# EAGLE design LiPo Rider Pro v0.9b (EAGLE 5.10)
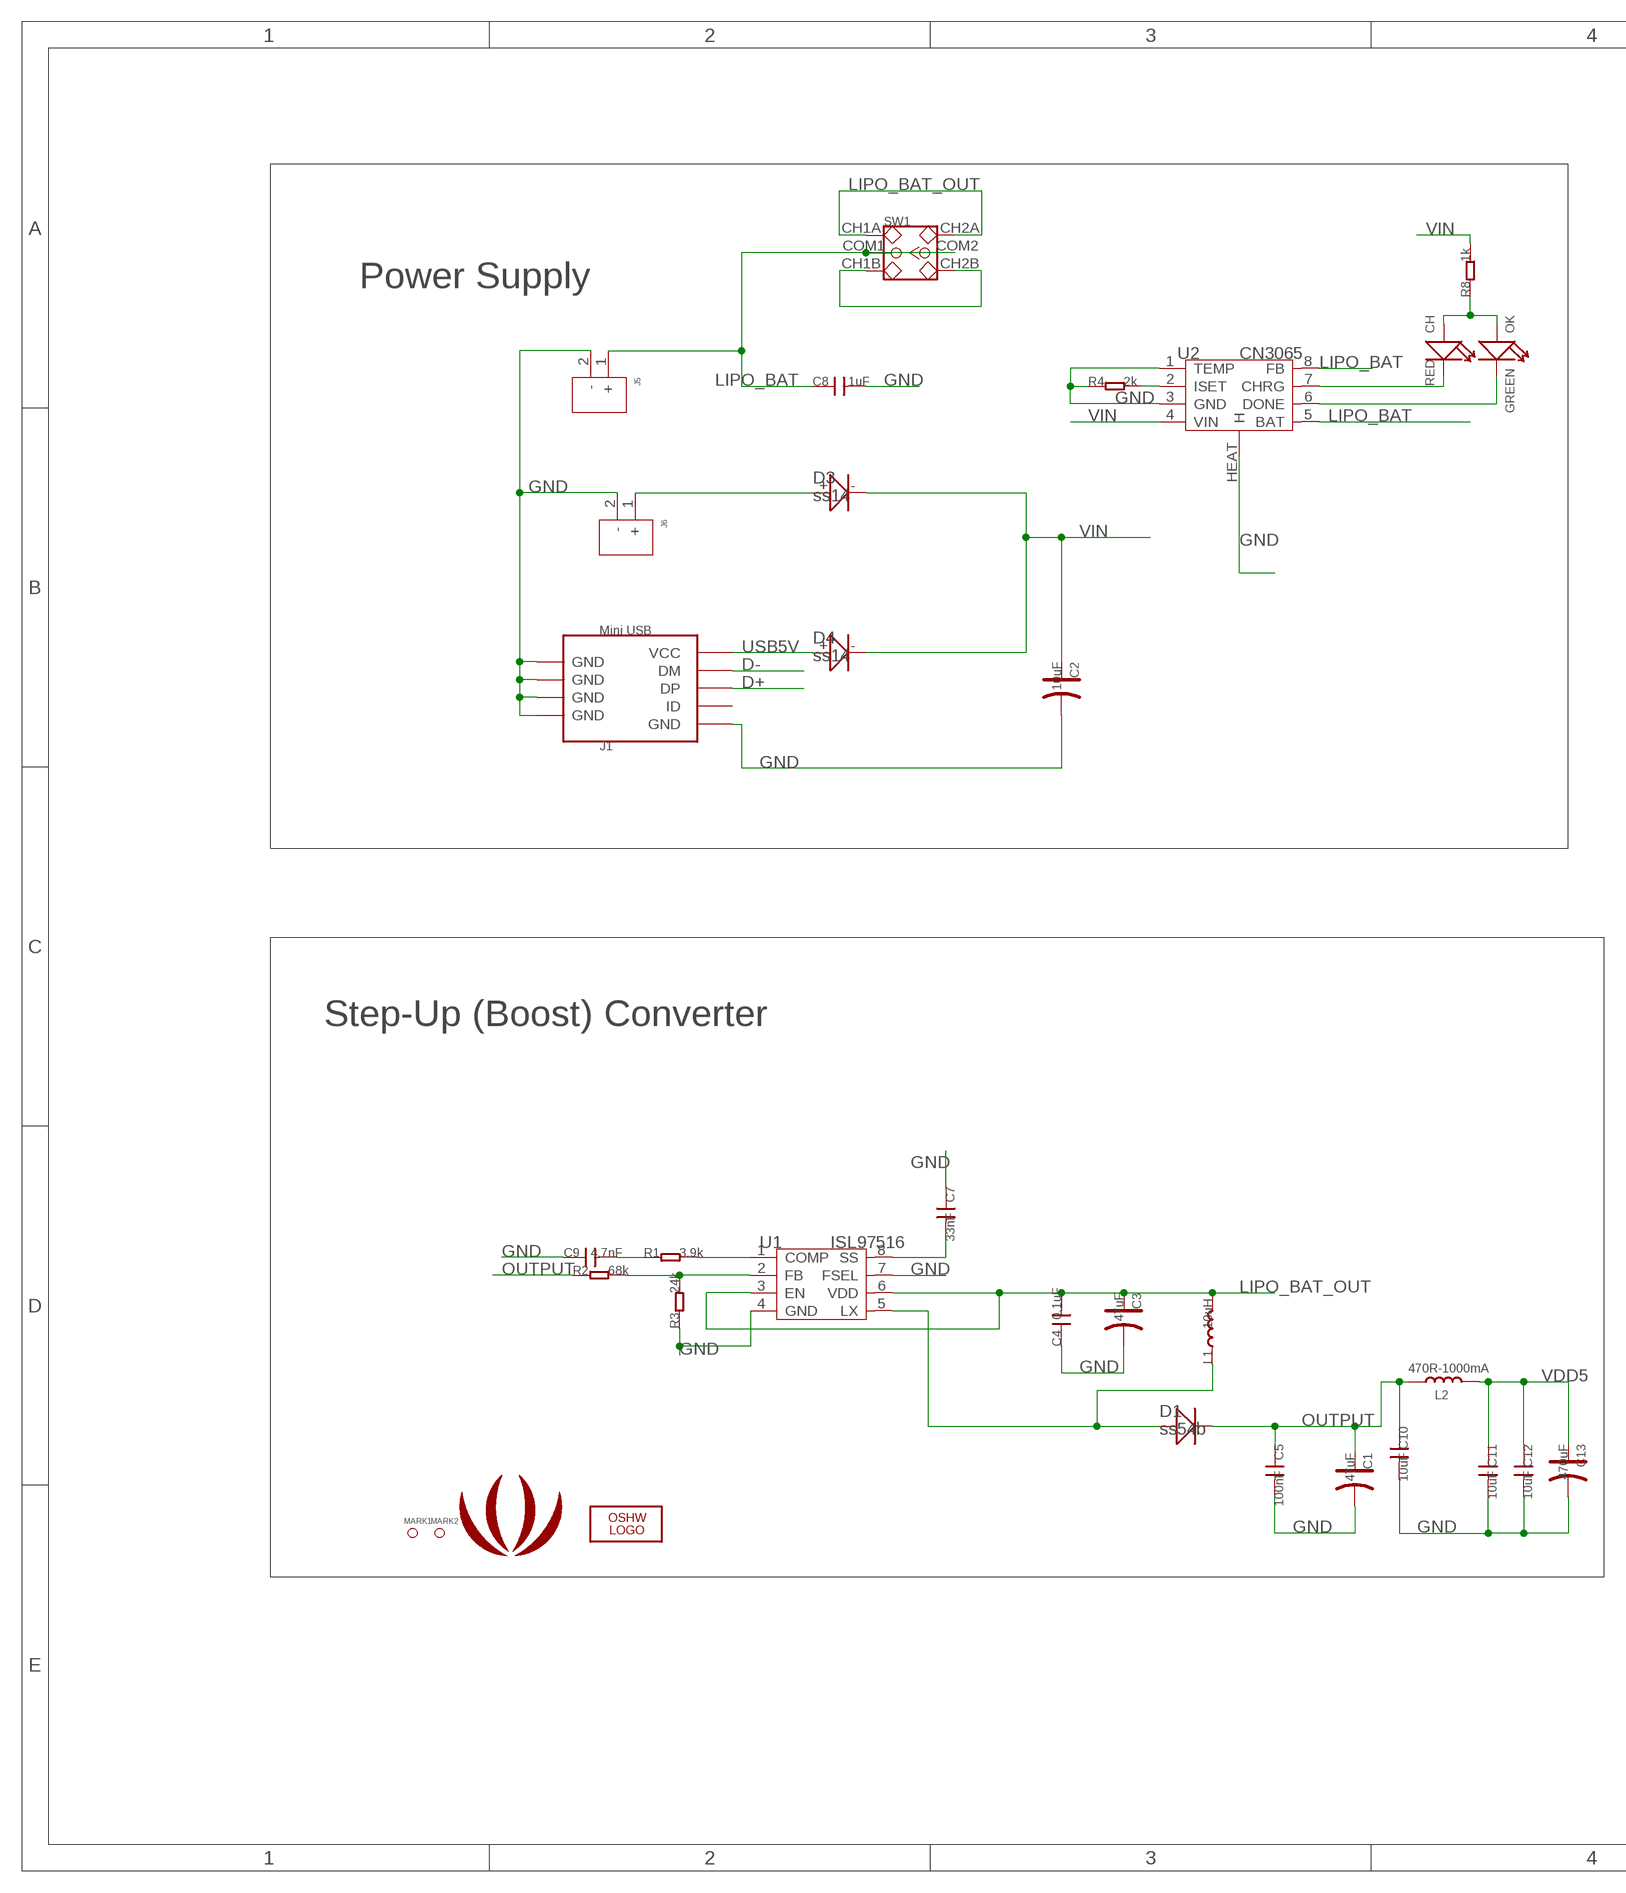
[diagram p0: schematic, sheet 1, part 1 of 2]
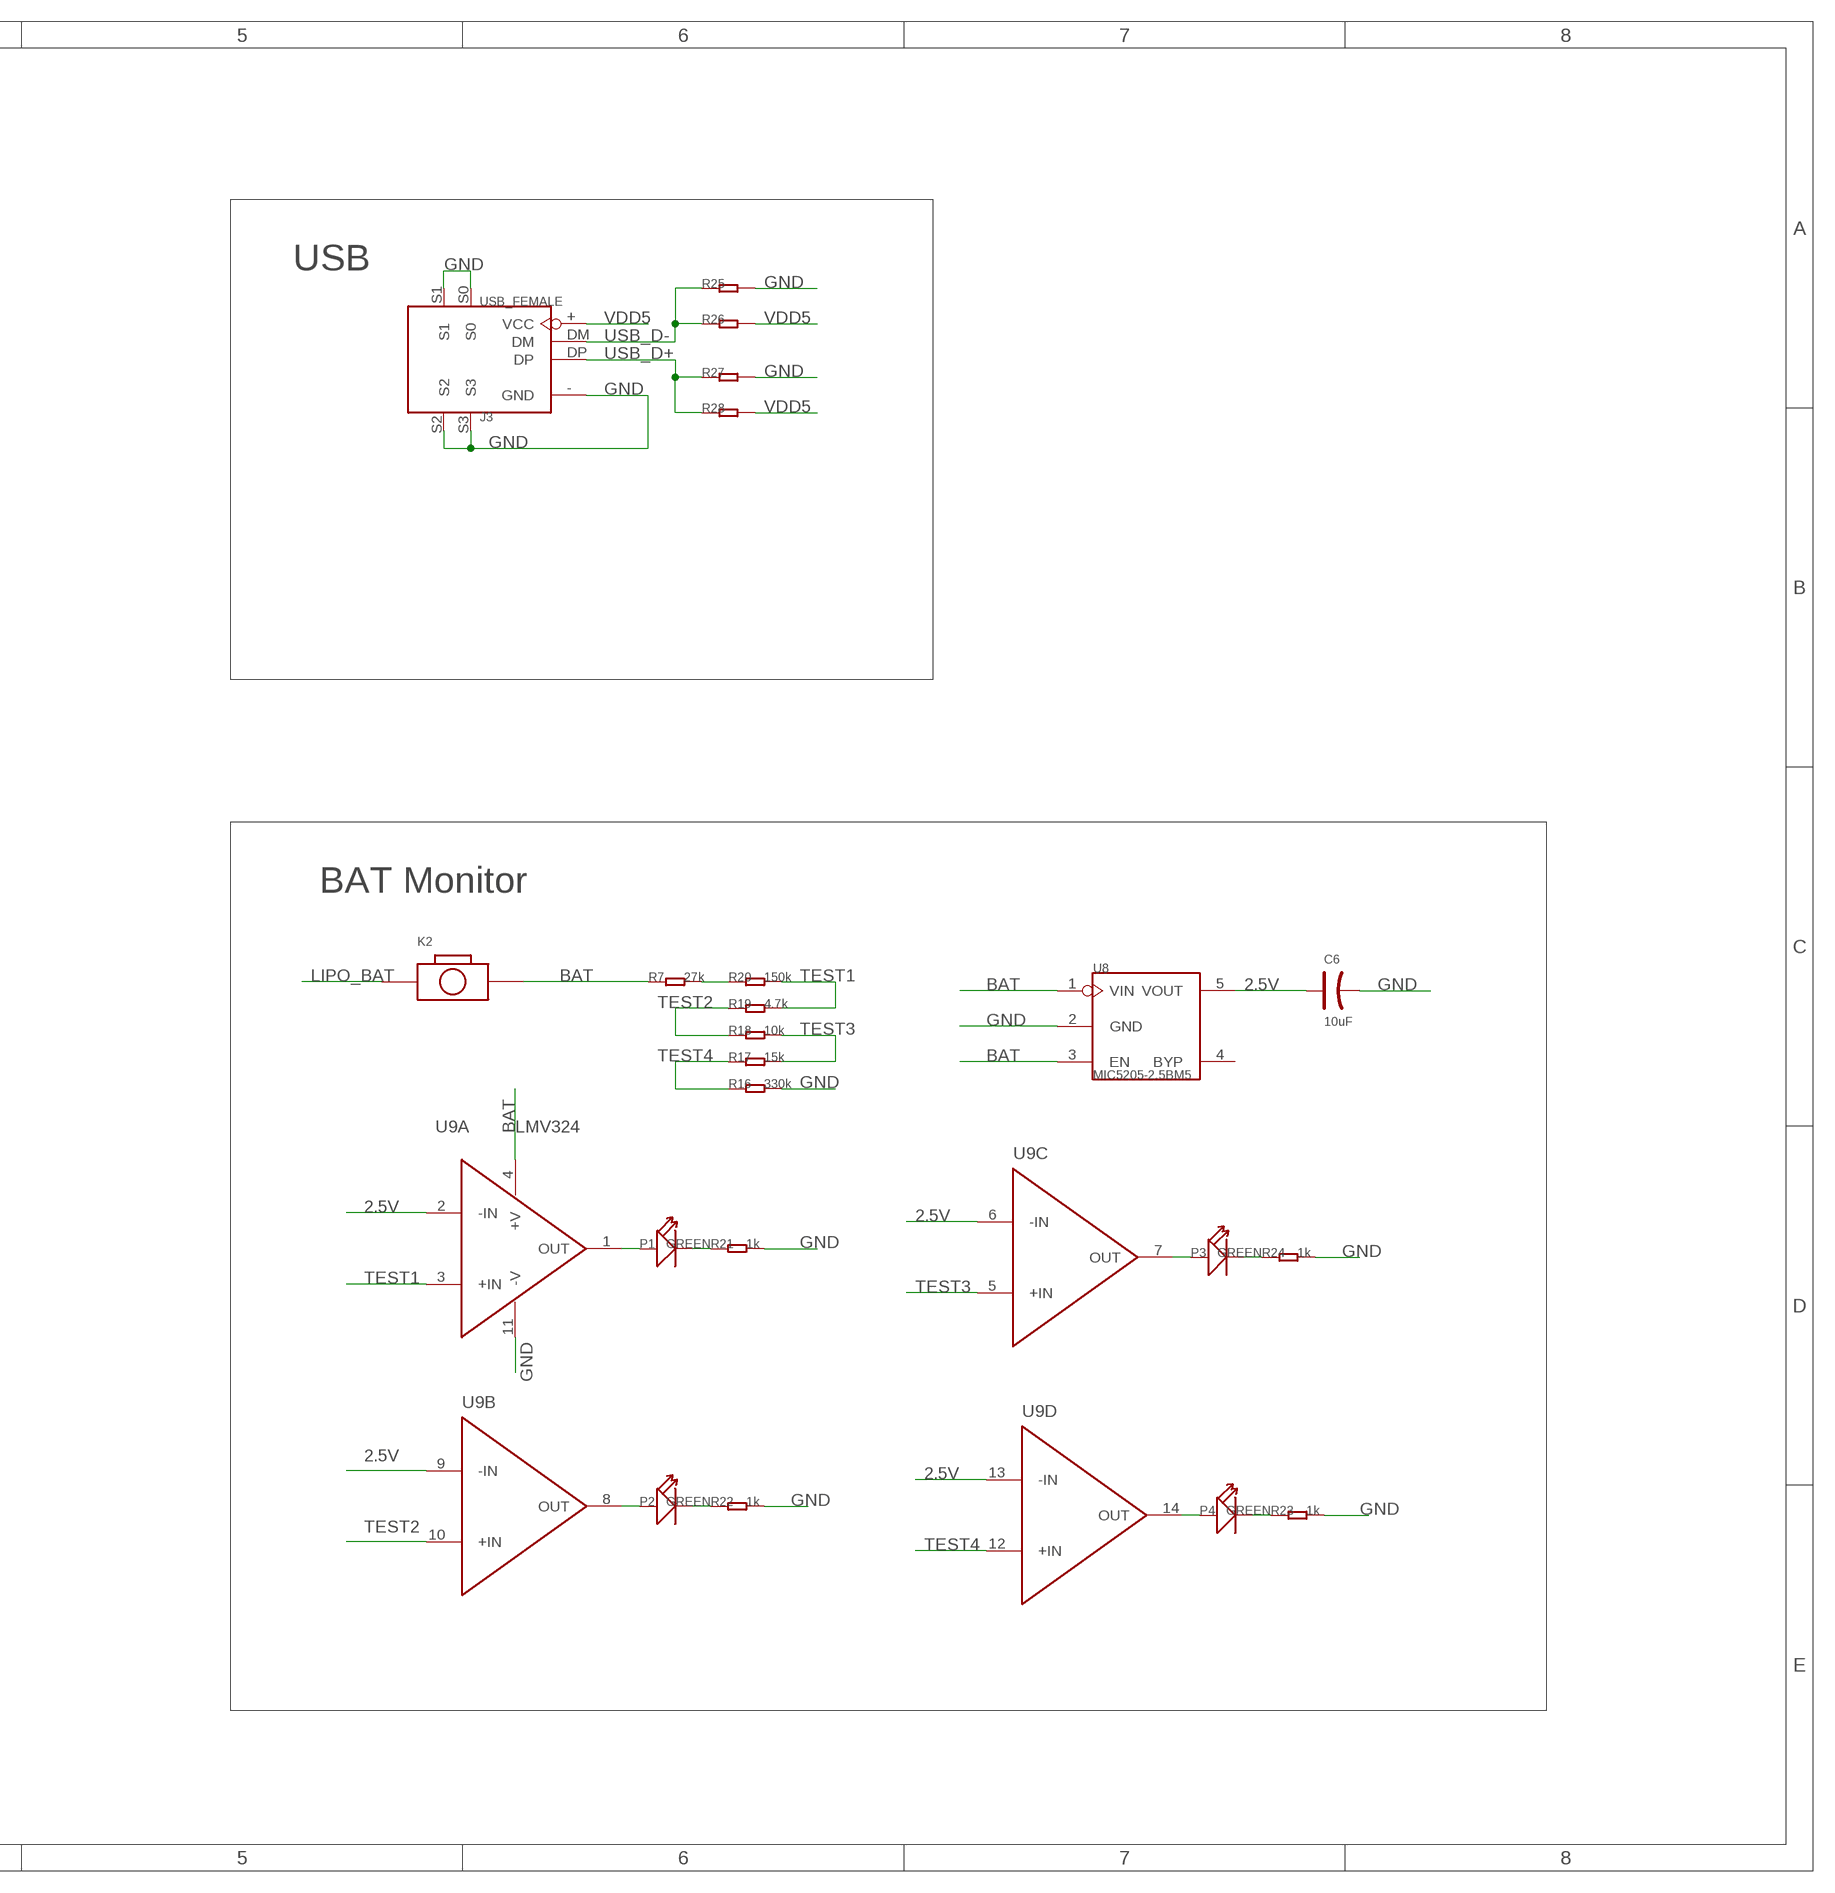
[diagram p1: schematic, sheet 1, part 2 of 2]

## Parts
C1  47uF  CAP_AVX_C  [AVX-C]
C2  10uF  CAP_AVX_B  [AVX-B]
C3  47uF  CAP_AVX_C  [AVX-C]
C4  0.1uF  C-0603  [0603]
C5  100nF  C-0603  [0603]
C6  10uF  CAP_AVX_B  [AVX-B]
C7  33nF  C-0603  [0603]
C8  1uF  C-0805  [0805]
C9  4.7nF  C-0603  [0603]
C10  10uF  C-0805  [0805]
C11  10uF  C-0805  [0805]
C12  10uF  C-0805  [0805]
C13  470uF  CAP_AVX_D  [AVX-D]
CH  RED  LED-0603  [D0603]
D1  ss54b  D-MBRS240LT3  [SMB]
D3  ss14  010-D2010  [D2010]
D4  ss14  010-D2010  [D2010]
J1  Mini USB  USB-MINIUSB-5P-STRONG  [MINI-5P]
J3  USB_FEMALE  USB-FEMALE-13.2X14.5  [FEMALE-13.2X14.5]
J5  JST-2P-POWER-SMD'2.0'  [2P-SMD-2.0-8X7.8]
J6  JST-2P-POWER-SMD'2.0'  [2P-SMD-2.0-8X7.8]
K2  BOTTON-2P-DIP  [2P-LEADED-90-3.56X7.62]
L1  10uH  L-PIO73  [PIO73]
L2  470R-1000mA  L0805  [0805]
LOGO1  LOGO-OSHW-FILLX0200-NT  [OSHW_FILLX200_NOTEXT]
MARK1  PAD-MARK  [ROUND-MARK-0.635]
MARK2  PAD-MARK  [ROUND-MARK-0.635]
OK  GREEN  LED-0603  [D0603]
P1  GREEN  LED-0603  [D0603]
P2  GREEN  LED-0603  [D0603]
P3  GREEN  LED-0603  [D0603]
P4  GREEN  LED-0603  [D0603]
R1  3.9k  R-0603  [0603]
R2  68k  R-0603  [0603]
R3  24k  R-0603  [0603]
R4  2k  R-0603  [0603]
R7  27k  R-0603  [0603]
R8  1k  R-0603  [0603]
R16  330k  R-0603  [0603]
R17  15k  R-0603  [0603]
R18  10k  R-0603  [0603]
R19  4.7k  R-0603  [0603]
R20  150k  R-0603  [0603]
R21  1k  R-0603  [0603]
R22  1k  R-0603  [0603]
R23  1k  R-0603  [0603]
R24  1k  R-0603  [0603]
R25  R-0204/5  [0204/5]
R26  R-0204/5  [0204/5]
R27  R-0204/5  [0204/5]
R28  R-0204/5  [0204/5]
SW1  SWITCH-2CH-6P'90'  [6P-LEADED-2CH-2.54-90-3.6X9.0]
U1  ISL97516  [MSOP8]
U2  CN3065  [DFN8]
U8  MIC5205-2.5BM5  MIC5025-SOT23-5  [SOT23-5]
U9  LMV324  [SO014]
U$1  LOGO-SEEEDSTUDIO-SILK  [LOGO_SILK]

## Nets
2.5V: C6.+ U8.5(VOUT) U9.2(A:-IN) U9.6(C:-IN) U9.9(B:-IN) U9.13(D:-IN)
BAT: K2.P$2 R7.1 U8.1(VIN) U8.3(EN) U9.4(A:+V)
CH: SW1.CH1B SW1.CH2B
D+: J1.3(DP)
D-: J1.2(DM)
GND: C1.- C2.- C3.- C4.1 C5.2 C6.- C7.1 C8.2 C9.1 C10.2 C11.2 C12.2 C13.- J1.5(GND) J1.GND@1(GND) J1.GND@2(GND) J1.GND@3(GND) J1.GND@4(GND) J3.-(GND) J3.S0 J3.S1 J3.S2 J3.S3 J5.2(-) J6.2(-) R3.1 R4.1 R16.2 R21.2 R22.2 R23.2 R24.2 R25.2 R27.2 U1.4(GND) U1.7(FSEL) U2.1(TEMP) U2.3(GND) U2.HEAT(H) U8.2(GND) U9.11(A:-V)
LIPO_BAT: C8.1 J5.1(+) K2.P$1 SW1.COM1 SW1.COM2 U2.5(BAT) U2.8(FB)
LIPO_BAT_OUT: C3.+ C4.2 L1.2 SW1.CH1A SW1.CH2A U1.3(EN) U1.6(VDD)
N$1: C7.2 U1.8(SS)
N$2: D1.+ L1.1 U1.5(LX)
N$3: D3.+ J6.1(+)
N$4: R1.2 U1.1(COMP)
N$5: C9.2 R1.1
N$6: R2.2 R3.2 U1.2(FB)
N$7: R4.2 U2.2(ISET)
N$8: CH.- U2.7(CHRG)
N$9: OK.- U2.6(DONE)
N$10: CH.+ OK.+ R8.1
N$20: R7.2 R20.1
N$25: P3.+ U9.7(C:OUT)
N$26: P4.+ U9.14(D:OUT)
N$28: P1.+ U9.1(A:OUT)
N$31: P2.+ U9.8(B:OUT)
N$33: P1.- R21.1
N$35: P2.- R22.1
N$36: P4.- R23.1
N$37: P3.- R24.1
OUTPUT: C1.+ C5.1 C10.1 D1.- L2.1 R2.1
TEST1: R19.2 R20.2 U9.3(A:+IN)
TEST2: R18.1 R19.1 U9.10(B:+IN)
TEST3: R17.2 R18.2 U9.5(C:+IN)
TEST4: R16.1 R17.1 U9.12(D:+IN)
USB5V: D4.+ J1.1(VCC)
USB_D+: J3.DP R27.1 R28.1
USB_D-: J3.DM R25.1 R26.1
VDD5: C11.1 C12.1 C13.+ J3.+(VCC) L2.2 R26.2 R28.2
VIN: C2.+ D3.- D4.- R8.2 U2.4(VIN)
Unconnected: J1.4(ID) U8.4(BYP)

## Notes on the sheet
- USB
- Power Supply
- BAT Monitor
- Step-Up (Boost) Converter

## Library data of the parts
C1 C3 C13 = Discrete:CAP*: Electrolytic Capacitors,Tantalum Capacitors and Super Capacitors
C2 C6 = Discreter:CAP*: Electrolytic Capacitors,Tantalum Capacitors and Super Capacitors
C4 C5 C7 C9-C12 = Discrete:C*: Ceramic Capacitors
C8 = Discreter:C*: Ceramic Capacitors
CH OK = Discrete:LED*
D1 = Discrete:D*
D3 D4 = Discrete:010-D*
J1 = Connector:USB-MINIUSB-5P
J3 = Connector:USB-FEMALE
J5 J6 = Connector:JST-2P-POWER-SMD
K2 = Discreter:BOTTON-2P
L1 L2 = Discrete:L*
LOGO1 = Logo:LOGO-OSHW-FILL
MARK1 MARK2 = Discreter:PAD-MARK
P1-P4 = Discreter:LED*
R1-R4 R8 R25-R28 = Discrete:R*
R7 R16-R24 = Discreter:R*
SW1 = Discrete:SWITCH-2CH-6P
U1 = IC:ISL97516
U2 = IC:CN3065
U8 = IC:MIC5025
U9 = IC (Miao Albert's conflicted copy 2011-05-27):LMV324
U$1 = Logo:LOGO-SEEEDSTUDIO

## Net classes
0 default: width 0.203 mm, drill 0.305 mm, clearance 0.127 mm

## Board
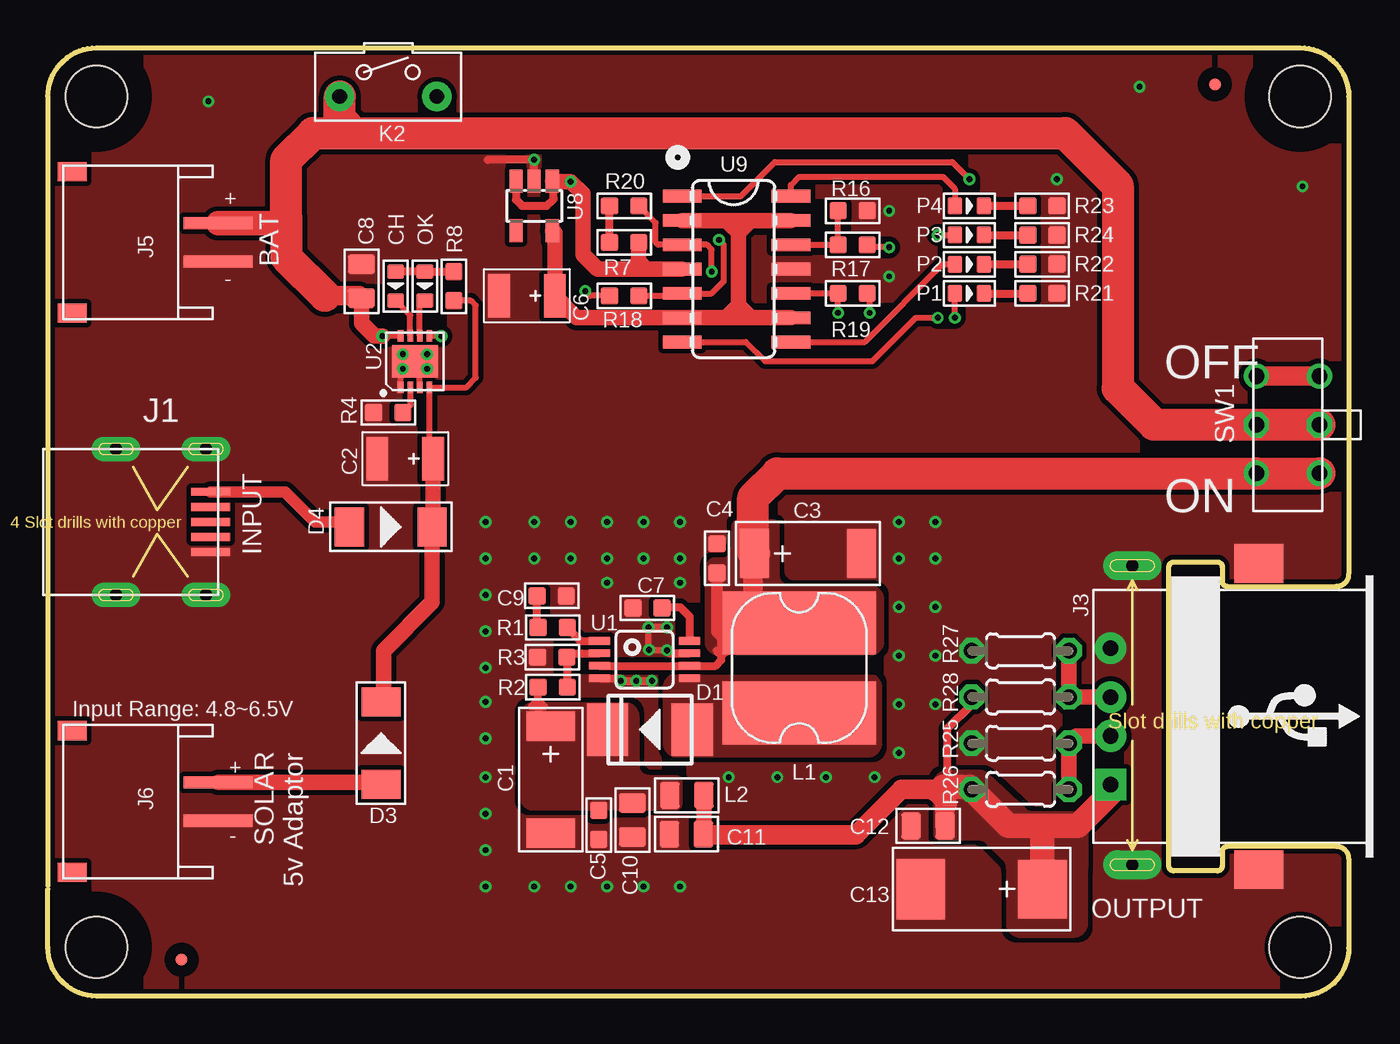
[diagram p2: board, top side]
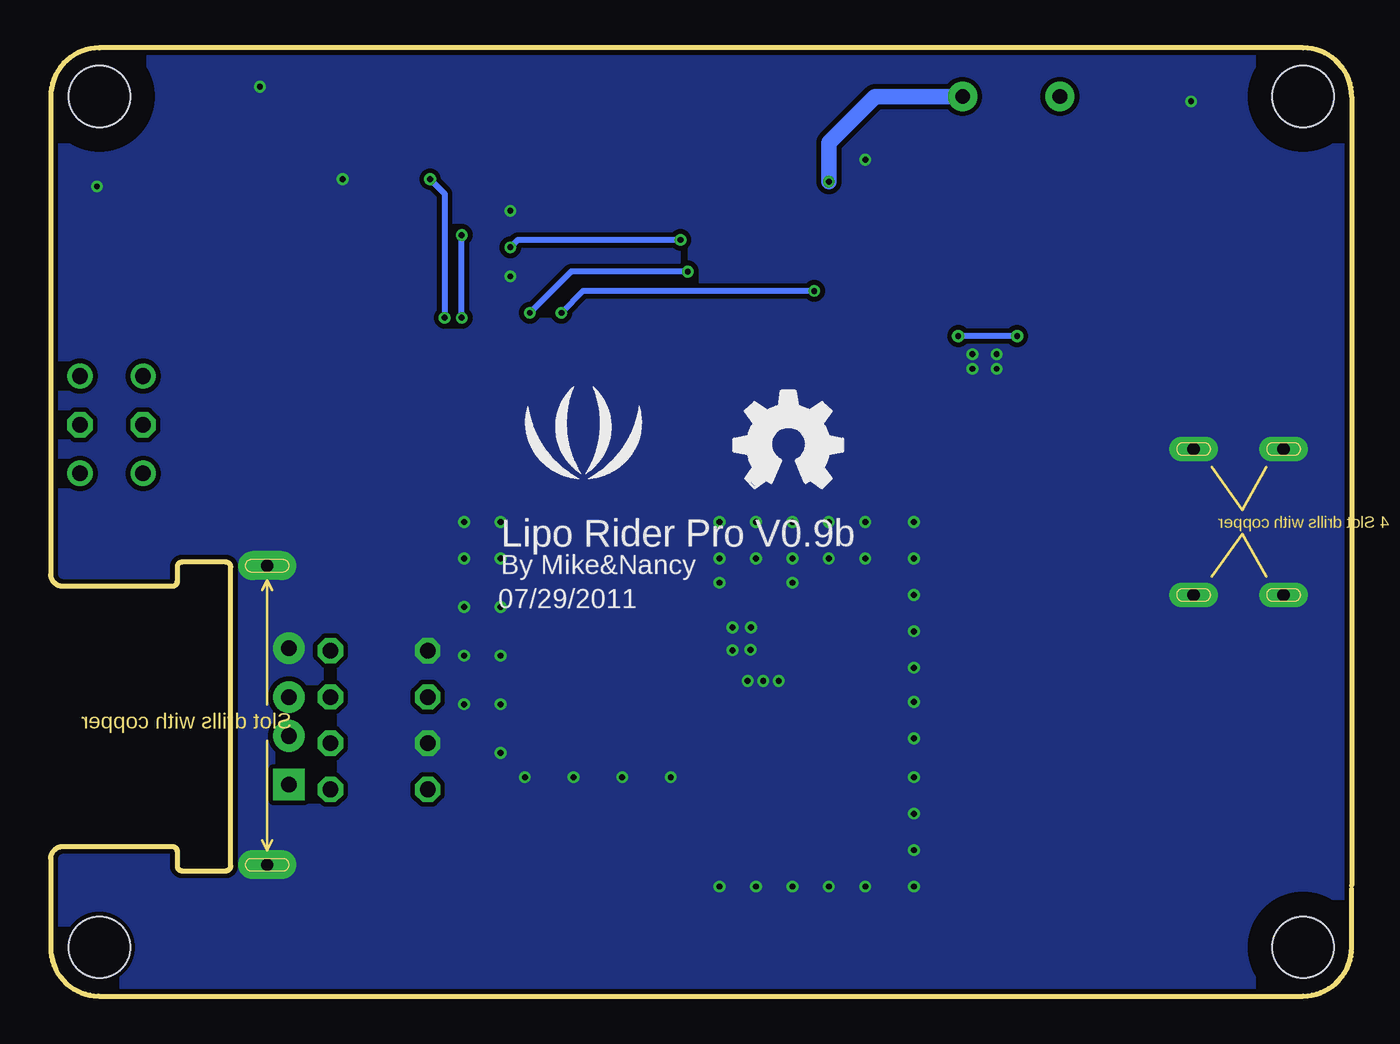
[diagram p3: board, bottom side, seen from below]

Size 67.94 x 49.53 mm. Coordinates in mm from the lower left corner, seen from the top.
Outline: 0,5.78 0,46.99 arc-90 2.54,49.53 65.41,49.53 arc-90 67.94,46.99 67.94,22.04 arc-90 67.31,21.4 61.59,21.4 arc-90 61.34,21.65 61.34,22.42 arc90 61.09,22.67 58.8,22.67 arc90 58.55,22.42 58.55,6.79 arc90 58.8,6.54 61.09,6.54 arc90 61.34,6.79 61.34,7.56 arc-90 61.59,7.81 67.31,7.81 arc-90 67.94,7.18 67.94,2.5 arc-90 65.44,0 2.54,0 arc-90 0,2.54 0,5.59
Copper layers (1*16): Top 0.035mm / dielectric 1.5mm / Bottom 0.035mm
Design rules "SeeedStudio_rule_no_angle_090911 *": minimum track width 6mil, minimum drill 12mil, track to track 6mil, track to pad 6mil, pad to pad 6mil, via to via 6mil, smd to smd 0mil, copper to edge 10mil, drill to drill 10mil, minimum pad ring 10mil, minimum via ring 6mil, stop-mask expansion 2mil, vias tented up to drill 25mil, thermal gap 10mil
Holes 3.2 mm at 2.54,46.99 2.54,2.54 65.41,46.99 65.41,2.54
tRestrict: area 0,44.5 to 5.1,49.5; area 62.9,44.5 to 67.9,49.5; area 0,0 to 5.1,5.1; area 35.6,17 to 43.4,17.6; area 35.2,17 to 35.8,17.2
bRestrict: area 62.9,44.5 to 67.9,49.5; area 0,0 to 5.1,5.1; area 0,44.5 to 5.1,49.5

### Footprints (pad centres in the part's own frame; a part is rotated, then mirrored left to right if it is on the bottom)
AVX-C = smd 1.524 x 2.54: + -2.794,0; - 2.794,0
AVX-B = smd 1.143 x 2.286: + -1.46,0; - 1.46,0
0603 = smd 0.889 x 0.889: 1 -0.762,0; 2 0.762,0
0805 = smd 1.016 x 1.397: 1 -0.889,0; 2 0.889,0
AVX-D = smd 2.54 x 3.048: + -3.175,0 | smd 2.54 x 3.175: - 3.175,0
D0603 = smd 0.762 x 0.889: + -0.762,0; - 0.762,0
SMB = smd 2.159 x 2.743: + 2.21,0; - -2.21,0
D2010 = smd 1.524 x 2.032: + -2.159,0; - 2.159,0
MINI-5P = smd 2.032 x 0.406: 1 0.381,-1.575; 2 0.381,-0.787; 3 0.381,0; 4 0.381,0.787; 5 0.381,1.575 | drill 0.635 pad 1.27 long: GND@1 0.635,3.81; GND@2 5.334,3.81; GND@3 5.334,-3.81; GND@4 0.635,-3.81
FEMALE-13.2X14.5 = drill 0.813 pad 1.651 square: + 0.889,-3.556 | drill 0.813 pad 1.651 round: - 0.889,3.556; DM 0.889,-1.016; DP 0.889,1.016 | smd 2.54 x 2.032: S0 8.636,8.001; S3 8.636,-8.001 | drill 0.635 pad 1.524 long: S1 2.032,7.874; S2 2.032,-7.747
2P-SMD-2.0-8X7.8 = smd 0.635 x 3.6: 1 -1,5.08; 2 1,5.08 | smd 1 x 1.5: P$1 -3.7,-2.54; P$2 3.7,-2.54
2P-LEADED-90-3.56X7.62 = drill 0.762 pad 1.524 round: P$1 0,2.54; P$2 0,-2.54
PIO73 = smd 8 x 3.3: 1 0,2.35; 2 0,-2.35
ROUND-MARK-0.635 = smd 0.635 x 0.635: P$1 0,0
0204/5 = drill 0.813 octagon: 1 -2.54,0; 2 2.54,0
6P-LEADED-2CH-2.54-90-3.6X9.0 = drill 0.813 pad 1.27 round: CH1A -2.54,-1.65; CH1B 2.54,-1.65; CH2A -2.54,1.65; CH2B 2.54,1.65 | drill 0.813 pad 1.27 octagon: COM1 0,-1.65; COM2 0,1.65
MSOP8 = smd 0.4 x 1.1: 1 -0.975,-2.35; 2 -0.325,-2.35; 3 0.325,-2.35; 4 0.975,-2.35; 5 0.975,2.35; 6 0.325,2.35; 7 -0.325,2.35; 8 -0.975,2.35
DFN8 = smd 0.3 x 0.6: 1 -0.75,-1.35; 2 -0.25,-1.35; 3 0.25,-1.35; 4 0.75,-1.35; 5 0.75,1.35; 6 0.25,1.35; 7 -0.25,1.35; 8 -0.75,1.35 | smd 2.4 x 1.7: HEAT 0,0
SOT23-5 = smd 0.69 x 1.2: 1 -0.95,-1.3; 2 0,-1.3; 3 0.95,-1.3; 4 0.95,1.3; 5 -0.95,1.3
SO014 = smd 0.66 x 2.032: 1 -3.175,-2.68; 2 -1.905,-2.68; 3 -0.635,-2.68; 4 0.635,-2.68; 5 1.905,-2.68; 6 3.175,-2.68; 7 4.445,-2.68; 8 4.445,2.997; 9 3.175,2.997; 10 1.905,2.997; 11 0.635,2.997; 12 -0.635,2.997; 13 -1.905,2.997; 14 -3.175,2.997

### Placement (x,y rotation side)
C1  26.26,11.3 270 top
C2  18.67,28.07 180 top
C3  39.7,23.11 0 top
C4  34.95,22.86 270 top
C5  28.78,8.94 270 top
C6  25.02,36.58 180 top
C7  31.32,20.27 0 top
C8  16.38,37.34 90 top
C9  26.31,20.9 180 top
C10  30.53,9.19 270 top
C11  33.35,8.46 180 top
C12  45.97,8.89 180 top
C13  48.77,5.59 180 top
CH  18.16,37.08 270 top
D1  31.45,13.92 0 top
D3  17.4,13.21 90 top
D4  17.91,24.51 0 top
J1  8.89,24.77 180 top
J3  54.61,14.61 0 top
J5  3.81,39.37 270 top
J6  3.81,10.16 270 top
K2  17.78,46.99 90 top
L1  39.24,17.14 180 top
L2  33.38,10.49 0 top
LOGO1  32.26,26.54 0 bottom
MARK1  6.99,1.91 0 top
MARK2  60.96,47.62 0 top
OK  19.68,37.08 270 top
P1  48.13,36.7 0 top
P2  48.13,38.23 0 top
P3  48.13,39.75 0 top
P4  48.13,41.27 0 top
R1  26.37,19.25 0 top
R2  26.37,16.13 0 top
R3  26.34,17.7 0 top
R4  17.78,30.48 0 top
R7  30.1,39.37 180 top
R8  21.21,37.08 270 top
R16  42.04,41.02 0 top
R17  42.04,39.24 0 top
R18  30.1,36.58 0 top
R19  42.04,36.7 0 top
R20  30.1,41.27 0 top
R21  51.94,36.7 0 top
R22  51.94,38.23 0 top
R23  51.94,41.27 0 top
R24  51.94,39.75 0 top
R25  50.8,13.21 180 top
R26  50.8,10.79 180 top
R27  50.8,18.03 180 top
R28  50.8,15.62 180 top
SW1  64.77,29.84 90 top
U1  31.17,17.58 270 top
U2  19.18,33.15 0 top
U8  25.4,41.27 180 top
U9  35.81,38.61 270 top
U$1  40.13,28.7 0 bottom

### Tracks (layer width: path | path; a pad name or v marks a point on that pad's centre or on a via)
2.5V
  Top 0.813: U8.5 26.48,39.84 C6.+ 27.62,35.43 U9.6 35.43,35.43 | 36.07,35.43 36.7,35.43 | 36.7,35.43 U9.9 | 36.07,40.51 U9.2 | 36.07,40.51 U9.13 | 35.43,35.43 36.07,35.43 | 36.07,35.43 36.07,36.07 | 36.07,39.88 36.07,40.51 | 36.07,39.88 35.56,40.39 | 36.07,39.88 36.58,40.39 | 36.07,36.07 36.7,35.43 | 36.07,36.07 36.07,39.88 | 35.43,35.43 36.07,36.07
BAT  (via drill 0.3 pad 0.61)
  Top 0.406: U8.3 24.45,41.59 24.77,41.27 26.06,41.27 26.42,41.63 26.42,42.51 U8.1
  Top 0.813: 30.48,37.97 28.7,37.97 27.94,38.73 27.94,41.91 v27.3,42.55 26.38,42.55 U8.1 | 30.48,37.97 U9.4 | 30.86,38.35 R7.1 | 30.86,38.35 31.11,38.1 | 30.48,37.97 30.86,38.35
  Bottom 0.813: K2.P$2 24.89,46.99 27.3,44.58 v27.3,42.55
CH
  Top 1.016: SW1.CH2B SW1.CH1B
GND  (via drill 0.3)
  Top 0.305: U2.3 19.43,32.38 v19.81,32.77 | U2.1 18.43,32.65 v18.54,32.77 | v32.33,18.06 31.39,18.06 31.37,18.03 31.37,19.3 32.26,19.3 32.38,19.18
  Top 0.406: U8.2 v25.4,43.69 22.99,43.69 | 32.99,17.9 U1.7 | v32.33,18.06 32.49,17.9 32.99,17.9 | 32.99,17.9 32.99,17.91 32.77,17.91 | U1.4 29.78,16.6 v29.92,16.46 30.68,16.46 30.73,16.51 | v30.73,16.46 31.45,16.46 31.5,16.51
  other vias: 52.7,42.67 43.94,41.02 43.94,37.59 65.53,42.29 8.38,46.74 57.02,47.5 22.86,11.43 22.86,13.46 22.86,15.37 22.86,19.05 22.86,9.53 22.86,7.62 22.86,20.95 31.39,18.08 22.86,17.14 22.86,5.71 25.4,5.71 27.3,5.71 29.21,5.71 33.02,5.71 31.11,5.71 22.86,22.86 25.4,22.86 27.3,22.86 29.21,22.86 31.11,22.86 33.02,22.86 33.02,21.59 29.21,21.59 33.02,24.77 31.11,24.77 29.21,24.77 27.3,24.77 25.4,24.77 22.86,24.77 44.45,24.77 44.45,22.86 44.45,20.32 44.45,17.78 44.45,15.24 44.45,12.7 46.35,24.77 46.35,15.24 46.35,17.78 46.35,20.32 46.35,22.86 32.33,19.25 31.37,19.25 31.55,16.46 18.54,33.53 19.81,33.53 35.56,11.43 38.1,11.43 40.64,11.43 43.18,11.43
  pour Bottom: -6.99,48.26 -5.71,48.26 -5.71,46.99 -6.99,46.99
  pour Top (isolate 0.254, rank 5, no thermals): -1.27,50.16 70.48,50.16 70.48,-1.27 -1.27,-1.27
  pour Bottom (isolate 0.254, rank 5, no thermals): -1.27,50.16 70.48,50.16 70.48,-1.27 -1.27,-1.27
LIPO_BAT  (via drill 0.3 pad 0.64)
  Top 0.305: v20.55,34.47 20,34.47 arc-45 U2.5 | U2.8 17.8,34.5 arc45 v17.48,34.47
  Top 0.406: SW1.COM1
  Top 0.813: v17.48,34.47 17.07,34.47 16.38,35.15 C8.1
  Top 1.016: 14.48,36.58 16.26,36.58 C8.1
  Top 1.27: J5.1 12.18,40.37 12.45,40.64
  Top 1.676: 15.24,45.72 K2.P$1 | 15.24,45.72 15.24,45.62 14.71,45.09 | 15.24,45.72 15.37,45.72 16,45.09 | 14.71,45.09 16,45.09 | 16,45.09 53.13,45.09 55.88,42.34 55.88,31.75 57.78,29.84 SW1.COM2 SW1.COM1 | 14.71,45.09 13.84,45.09 12.45,43.69 12.45,40.64 12.45,38.61 14.48,36.58
  Bottom 0.305: v17.48,34.47 v20.55,34.47
LIPO_BAT_OUT
  Top 0.406: U1.3 U1.6 34.89,17.25 35.18,17.55 35.18,17.78 | L1.2 38.92,19.18 36.58,19.18 | 35.18,17.78 35.18,18.8 | 36.58,19.18 35.43,19.18 35.12,18.86 35.05,18.8 36.2,18.8 36.58,19.18 | 35.18,17.78 35.05,17.91 | 35.05,17.91 34.92,18.03 | 35.18,17.78 35.43,18.03 | 38.73,19.05 36.2,19.05 35.05,17.91
  Top 0.61: C4.2 34.95,19.02 35.12,18.86 38.54,18.86 38.73,19.05 | 36.58,19.18 36.58,19.43 36.83,19.68
  Top 1.016: 36.83,19.68 36.83,23.19
  Top 1.676: C3.+ 36.83,23.19 36.83,26.04 38.1,27.3 SW1.CH2A SW1.CH1A
  pour Top (isolate 0.254, no thermals): 43.56,20.7 arc90 42.93,21.34 38.73,21.34 arc-90 38.1,21.97 38.1,24.51 arc90 37.85,24.77 36.07,24.77 arc90 35.81,24.51 35.81,23.5 arc-90 35.18,22.86 35.05,22.86 arc90 34.42,22.23 34.42,18.54 arc90 35.05,17.91 42.93,17.91 arc90 43.56,18.54
  pour Top (isolate 0.254, no thermals): 43.56,20.7 arc90 42.93,21.34 38.73,21.34 arc-90 38.1,21.97 38.1,24.51 arc90 37.85,24.77 36.07,24.77 arc90 35.81,24.51 35.81,23.5 arc-90 35.18,22.86 35.05,22.86 arc90 34.42,22.23 34.42,18.54 arc90 35.05,17.91 42.93,17.91 arc90 43.56,18.54
N$1
  Top 0.406: U1.8 33.52,19.82 33.02,20.32 32.13,20.32 C7.2
N$2
  pour Top (isolate 0.254, no thermals): 32.89,12.57 arc-90 32.26,13.21 32.26,16.13 arc-90 32.89,16.76 42.8,16.76 arc-90 43.43,16.13 43.43,13.21 arc-90 42.8,12.57
N$3
  Top 0.813: J6.1 17.29,11.16 D3.+
N$4
  Top 0.406: U1.1 27.83,18.55 R1.2
N$5
  Top 0.406: C9.2 25.55,19.3 R1.1
N$6
  Top 0.406: U1.2 27.3,17.9 R3.2 27.13,17.68 R2.2
N$7
  Top 0.305: U2.2 18.93,30.86 R4.2
N$8
  Top 0.305: U2.7 18.93,35.56 CH.-
N$9
  Top 0.305: U2.6 19.43,36.06 OK.-
N$10
  Top 0.406: CH.+ OK.+ R8.1
N$20
  Top 0.406: R7.2 R20.1
N$25  (via drill 0.3 pad 0.61)
  Top 0.305: U9.7 36.45,34.16 37.46,33.16 43.06,33.16 45.34,35.43 v46.48,35.43 | v46.48,39.75 P3.+
  Bottom 0.305: v46.48,35.43 v46.48,39.75
N$26
  Top 0.305: U9.14 38.81,42.37 39.24,42.8 46.74,42.8 47.37,42.16 P4.+
N$28  (via drill 0.3 pad 0.61)
  Top 0.305: U9.1 36.2,41.78 37.97,43.56 47.24,43.56 v48.13,42.67 | v47.37,35.43 P1.+
  Bottom 0.305: v47.37,35.43 47.37,41.91 v48.13,42.67
N$31
  Top 0.305: U9.8 42.66,34.16 46.73,38.23 P2.+
N$33
  Top 0.406: P1.- R21.1
N$35
  Top 0.406: P2.- R22.1
N$36
  Top 0.406: P4.- R23.1
N$37
  Top 0.406: P3.- R24.1
OUTPUT
  Top 0.254: C1.+ 25.83,14.1 arc-90 25.58,14.35 25.58,14.38 arc90 25.6,14.4 25.6,15.44 | 25.58,15.44 arc-90 25.6,15.42 25.6,14.38
  Top 0.406: 25.6,15.44 25.6,14.38 | 25.6,15.44 R2.1 | 25.27,15.11 25.6,15.44 | 25.58,15.44 25.91,15.11
  pour Top (isolate 0.254, no thermals): 25.4,9.8 arc-90 24.77,10.44 24.77,14.61 arc-90 25.4,15.24 30.12,15.24 arc-90 30.76,14.61 30.76,12.06 arc90 31.39,11.43 32.77,11.43 arc-90 33.02,11.18 33.02,10.06 arc-90 32.77,9.8
TEST1  (via drill 0.3 pad 0.61)
  Top 0.305: R20.2 31.75,40.39 31.75,39.37 31.88,39.24 U9.3 34.42,39.24 34.67,38.99 v34.67,37.85 | v42.93,35.69 42.93,36.58 R19.2
  Bottom 0.305: v34.67,37.85 40.77,37.85 v42.93,35.69
TEST2  (via drill 0.3 pad 0.61)
  Top 0.305: R18.1 28.32,36.58 v28.07,36.83 | v41.27,35.69 R19.1 U9.10
  Bottom 0.305: v28.07,36.83 40.13,36.83 v41.27,35.69
TEST3  (via drill 0.3 pad 0.61)
  Top 0.305: R18.2 33.01,36.58 U9.5 34.67,36.7 35.31,37.34 35.31,39.24 v35.05,39.5 | v43.94,39.12 42.93,39.12 R17.2
  Bottom 0.305: v35.05,39.5 43.56,39.5 v43.94,39.12
TEST4
  Top 0.305: U9.12 R17.1 R16.1
USB5V
  Top 0.406: 15.49,24.77 D4.+
  Top 0.61: J1.1 12.39,26.34 13.97,24.77 15.49,24.77
USB_D+
  Top 0.813: J3.DP R28.1 R27.1
USB_D-
  Top 0.813: J3.DM 53.72,13.59 R25.1 R26.1
VDD5
  Top 0.406: 47.5,10.92 47.75,10.92 48.13,10.92 | R28.2 48.26,15.24 46.99,13.97 46.99,10.92
  Top 0.813: L2.2 34.27,8.48 C11.1
  Top 1.016: 46.86,10.79 C12.1 | 46.86,10.79 46.74,10.92 | 45.97,10.79 46.86,10.79 | C11.1 arc45 34.3,8.43 42.22,8.43 44.58,10.79 45.97,10.79 | 45.97,10.79 arc-45 46.41,10.61 46.99,10.03
  Top 1.27: 51.56,8.89 50.16,8.89 R26.2 48.13,10.92 | 51.56,8.89 53.79,8.89 55.5,10.6 J3.+ | 46.74,10.92 46.99,10.92 47.75,10.92 | C13.+ 51.94,8.51 51.56,8.89
  pour Top (isolate 0.254, rank 3, no thermals): -6.99,45.72 -5.71,45.72 -5.71,44.45 -6.99,44.45
  pour Top (no thermals): 50.16,3.81 arc90 50.8,3.17 53.57,3.17 arc90 54.2,3.81 54.23,9.53 51.43,9.53 arc-43 51,9.7 49.08,11.51 arc43 48.64,11.68 46.99,11.68 arc90 46.35,11.05 46.35,8.51 arc90 46.61,8.26 48.63,8.26 arc-45 49.08,8.07 49.98,7.17 arc-45 50.16,6.72
VIN
  Top 0.305: R8.2 22.1,36.32 22.35,36.07 22.35,32.3 21.84,31.8 U2.4 19.93,28.27 C2.+
  Top 0.813: C2.+ 20.13,24.57 D4.- 20.07,20.57 17.53,18.03 17.53,15.49 D3.-

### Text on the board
tPlace: + | BAT | - | OFF | ON | Input Range: 4.8~6.5V | + | - | SOLAR | 5v Adaptor
bPlace: Lipo Rider Pro V0.9b | By Mike&Nancy | 07/29/2011
tNames: INPUT | OUTPUT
